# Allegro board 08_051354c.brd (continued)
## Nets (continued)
UNNAMED_7_CAP_I150_N1: C21.1 R76.2(N2)
UNNAMED_7_CAP_I151_N2: A1.6 C29.2(N2) R31.1
UNNAMED_7_CAP_I152_N1: A1.4 C65.1 R33.1
UNNAMED_7_ICFAN3121_I89_EN: R117.2(N2) R118.1 U6.3
UNNAMED_7_ICFAN3121_I89_IN: R5.2(N2) U6.2
UNNAMED_7_MN34906BL_I91_HL: R66.2(N2) U1.17
UNNAMED_7_RES_I93_N2: Q1.5 Q1.6 R26.2(N2)
UNNAMED_10_ADDI9036_I362_AUXINA: C57.2(N2) R72.1 R73.2(N2) RT1.2(N2) U4.E7
UNNAMED_10_ADDI9036_I362_DNC3: R89.1 U4.E3
UNNAMED_10_ADDI9036_I362_DNC4: R88.1 U4.F4
UNNAMED_10_ADDI9036_I362_I2CSCL: R28.2(N2) R41.2(N2) U4.G5
UNNAMED_10_ADDI9036_I362_I2CSDA: R3.2(N2) R6.2(N2) U4.F5
UNNAMED_10_ADDI9036_I362_MTEST: R2.2(N2) U4.K3
UNNAMED_10_FERRITE_I381_N1: C5.1 E1.1 R1.2(N2) Y1.4(VDD)
UNNAMED_10_ICAT24CM01_I285_A2: R47.1 R54.2(N2) U5.3
UNNAMED_10_ICAT24CM01_I285_WP: R55.1 R60.2(N2) U5.7(WP)
UNNAMED_10_RES_I124_N1: R1.1 Y1.1
UNNAMED_10_RES_I290_N1: R62.1 R63.2(N2) U5.2
UNNAMED_10_RES_I374_N1: R110.1 Y1.3
UNNAMED_12_ADT7410_I215_A0: R105.1 R106.2(N2) U13.3
UNNAMED_12_ADT7410_I215_A1: R102.1 R103.2(N2) U13.4
UNNAMED_12_ICFSA642_I1_OEN: R90.2(N2) U7.8
UNNAMED_12_ICFSA642_I193_OEN: R84.1 U11.8
UNNAMED_12_ICPCA9517A_I144_EN: R101.1 U8.5
UNNAMED_12_ICPCA9517A_I227_EN: R24.2(N2) U9.5
UNNAMED_12_ICPCA9517A_I229_EN: R4.2(N2) U14.5
UNNAMED_12_RES_I54_N1: R91.1 S1.1(NO)
UNNAMED_12_RES_I55_N2: R36.2(N2) S1.3
VD: U4.F1
VL: R10.1 R53.2(N2) R70.2(N2)
VL_AFE: C20.2(N2) C27.1 R10.2(N2) U4.K11(VL)
VLD: P21.2 P21.4 P21.6 P21.8 P21.10 P21.12 P21.14 P21.16 P21.18(N9) P21.20 P21.22 P21.24 R25.1 R39.1 R108.2(N2)
VSUB: C44.1 C55.1 C64.1 R8.2(N2) R56.1 R111.1 R117.1 U6.1 U6.8(VDD2)

Pads without a net: P1 11 12 16 17 18 19 20 21 22 23 24 25 26 27 28 29 30; P3 3 5 15 17 20 21 22 23 26 27 28 29 33 35 36 38 39 41 45 47 51 53 57 59 60; P4 3 4 5 6 7 9 11 12 13 14 16 18 20 22 30 31 32 33 34 35 36 37 38; P21 17 19 21 23 25 26 28 41 43 45 47 49 51 53 55 57 59; S2 3; U1 1 7 10 12 25 26 31 32 34 38; U2 24 26 27; U3 6; U4 D4 D5 E5 F6 F7 F8 F9 G6 G7 H6 K5 K9 L2 L3 L9; U5 1; U7 7 24; U10 3 4 8; U11 7 24

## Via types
v1: diameter 0.508, hole 0.254, TOP to BOTTOM, 317 vias
v2: diameter 0.635, hole 0.305, TOP to BOTTOM, 227 vias
v3: diameter 0.457, hole 0.203, TOP to BOTTOM, 19 vias
v4: diameter 0.254, hole 0.127, TOP to L2_GND, 73 vias
v5: diameter 0.254, hole 0.127, L2_GND to L3_SIG, 35 vias

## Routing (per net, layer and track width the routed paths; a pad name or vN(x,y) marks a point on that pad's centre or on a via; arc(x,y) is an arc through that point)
5V_LD: length 4.7
  BOTTOM w0.254: U2.16 22.8,29.53 v1(22.61,29.34)
  BOTTOM w0.279: U2.19 22.86,31.03 22.86,31.04 ; 22.78,31.52 22.8,31.53 U2.20
  BOTTOM w0.508: R15.1 21.84,22.99 v1(21.97,23.11) ; v1(32.24,23.85) 32.05,24.04 32.03,24.04 31.81,24.26 R16.1
  vias: v1(50.5,23.44) v1(50.5,22.68) v1(50.47,21.92) v1(50.47,21.16) v2(7.49,23.37) v2(7.49,22.35) v2(7.49,21.34) v2(8.51,21.34) v2(8.64,23.38) v2(9.53,23.38) v2(16.76,33.4) v2(16.76,32.26) v2(16.76,30.99) v2(17.78,33.4)
5VCC: length 11
  TOP w0.508: R35.1 v1(34.29,22.61) ; R37.1 v1(38.95,10.29) ; R85.1 v1(37.47,22.61) ; R75.1 v1(42.63,10.25)
  BOTTOM w0.508: v1(5.58,30.86) 5.58,30.81 5.57,30.79 E2.2 5.57,27.14 E3.1 2.62,27.01 C49.2
  vias: v1(22.4,19.56) v1(22.43,18.8) v1(23.11,19.56) v1(23.11,18.8)
9VDD: length 127.6
  TOP w0.133: U4.K10 77.92,25.43
  TOP w0.305: 77.92,25.43 78.32,25.83 79.46,25.83 79.72,25.56 C15.1
  TOP w0.508: C15.1 80.36,25.52 81.29,25.52 C12.1 82.86,24 85.6,24 v1(86.11,24.51) ; R9.1 v2(115.87,21.34)
  L8_SIG w0.305: v1(95.83,7.75) v1(95.07,7.75) 92.82,7.75 90.53,10.03 80.14,10.03 77.98,7.87 69.7,7.87 64.67,2.85 30.88,2.85 24.08,9.65 24.08,13.31 21.21,16.18 21.21,20.45 14.22,27.43 14.22,34.7 v1(10.63,38.3)
  BOTTOM w0.133: R26.1 110.81,26.99 110.54,26.72 Q1.4
  BOTTOM w0.254: R26.1 v2(112.27,26.99)
  BOTTOM w0.508: R71.2 v2(93.82,24.38) ; R104.1 v1(10.63,38.3)
GND: length 303.6
  TOP w0.133: v2(100.98,11.68) 101.54,11.12 U12.C2
  TOP w0.165: U4.D6 v4(73.9,23.41)
  TOP w0.254: v1(61.72,22.23) 61.67,22.17 P21.34 ; 45.73,21 P1.7 ; 73.36,34.68 C6.2 ; A1.PAD A1.2 109.6,22.48 109.58,22.5 109.55,22.48 v1(109.45,22.58) ; 41.21,6.33 C85.2 41.21,5.1 ; v1(60.83,18.75) 60.82,18.75 60.18,18.11 59.48,18.11 59.42,18.17 P21.50 ; 82.29,9.01 C69.1 81.55,9.71 ; U4.B7 v4(73.9,23.41) ; C11.2 80.07,29.42 ; v1(62.26,17.02) 61.33,16.09 59.46,16.09 59.39,16.16 P21.58 ; 83.05,38.29 U8.4 84.06,38.9 ; v4(73.4,22.41) U4.C5 ; 45.73,15 P1.1 ; 74.47,16.32 C54.2 73.73,17.02 ; U4.G10 v4(76.4,24.91) v4(76.9,24.91) ; v1(59.46,17.17) P21.54 ; v4(74.9,24.41) U4.E10 U4.D10 v4(73.9,24.91) U4.C9 v4(73.4,24.41) ; 45.73,18 P1.4 ; 82.46,9.27 U13.7 ; C82.1 83.8,21.64 ; 38.67,5.1 C84.2 ; v1(60.83,20.17) P21.42 ; P21.30 59.11,23.17 59.78,23.84 v1(59.78,24.2) ; P21.46 v1(59.42,19.17) ; U4.E2 v4(74.4,20.91) ; v1(59.44,21.17) P21.38 ; DS1.C 12.42,37.1 ; Q2.4 17.03,40.22 ; U4.B3 v4(73.9,21.41) ; 12.42,43.57 12.42,43.46
  TOP w0.305: P21.PAD2 v2(55.05,29.08) P21.PAD1 v2(55.05,32.73) ; Q2.1 15.08,37.66 ; Q2.1 15.73,38.36 ; Q2.1 v1(15.73,36.93) ; v2(55.05,13.01) P21.PAD4 v2(55.05,16.73) P21.PAD3 ; C16.2 69.52,20.82 69.5,20.8 v1(69.32,20.99) ; C23.2 v1(69.16,18.66) ; v2(81.76,38.61) 82.06,38.9 U8.4 ; v1(69.35,19.67) 69.36,19.65 69.37,19.65 69.41,19.62 69.41,19.62 69.48,19.55 C31.2 ; 17.69,39.56 Q2.4 17.03,38.9 ; C85.2 v1(40.39,5.71) ; 26.19,17.81 25.39,18.6 U10.19 ; U10.13 20.42,21.31 ; C26.2 v1(69.35,25.7) ; C14.2 70.15,22.59 v1(69.92,22.35) ; v1(75.49,16.76) C19.2 ; C84.2 v1(39.5,5.71) ; v1(71.63,16.64) 72.05,16.64 C53.1 ; U10.2 27.67,20.81 v1(27.94,21.08)
  TOP w0.381: v2(99.49,19.81) 99.23,19.55 U1.20 ; U1.29 97.31,25.76 v2(97.07,25.53)
  TOP w0.406: U1.24 99.35,22.51 ; v2(99.45,21.21) U1.22 ; U1.6 v2(90.25,23.16)
  TOP w0.508: v2(103.38,12.97) 103.38,12.33 C79.2 104.65,12.31 v2(104.65,12.97) ; C72.2 v1(27.81,24.29) ; v1(78.84,14.35) 79.02,14.53 C77.1 ; C24.2 v1(62.52,22.41) ; C57.1 72.91,34.6 v1(72.89,34.62) ; P1.1 46.96,14.36 v2(47.12,14.21) ; v2(72.27,4.29) 73.35,4.29 C1.1 73.66,3.62 ; 91.2,13.78 R103.1 v2(92.22,12.95) ; C67.1 27.27,43.27 ; C67.1 27.27,41.19 ; C67.1 v2(26.16,42.16) ; v1(3.29,36.7) R36.1 4.02,35.81 ; v1(32.26,24.77) 32,24.51 R48.2 ; C86.1 50.7,11.47 ; C86.1 51.68,10.16 ; C86.1 49.72,10.16 ; C86.1 50.7,8.85 ; C13.2 v1(84.39,33.21) ; C13.2 v1(82.68,34.92) ; C13.2 v1(80.64,33.21) ; v1(69.39,34.82) 69.65,34.57 70.24,34.57 RT1.1 70.37,35.23 70.35,35.26 v1(70.35,35.26) ; C77.1 80.03,15.35 ; C77.1 77.97,15.35 ; 14.47,7.18 P31.2 ; P31.2 14.47,3.58 ; P31.2 12.65,5.38 ; P31.2 16.18,5.38 v2(16.51,5.71) ; 16.08,11.48 P31.3 ; P31.3 14.47,9.68 ; P31.3 14.47,13.28 ; P31.3 14.44,11.51 v2(12.78,11.51) ; v1(115.32,25.76) C29.1 114.47,26.49 ; C69.1 v2(80.54,9.01) ; v1(64.55,29.64) C61.2 66.34,29.16 67.9,27.6 C10.2 ; C83.1 71.37,29.6 v1(71.37,30.31) ; v2(48.3,23.31) 48.3,23.49 47.79,24 P1.10 ; C5.2 v1(65.31,25.38) ; 74.27,35.66 C6.2 v1(75.18,34.68) ; v1(78.25,29.41) 78.26,29.42 C11.2 79.17,30.3 ; C33.2 v1(76.88,16.36) ; C33.2 76.18,17.07 ; C33.2 77.7,17.07 ; R73.1 72.01,34.14 v1(72.01,34.67) ; v1(21.34,25.03) C74.2 ; v1(70.14,14.19) C7.2 ; C63.1 81.65,42.16 ; C63.1 v2(80.91,43.37) ; C63.1 80.18,42.16 ; P1.4 v1(48.69,18) ; C62.1 v2(113.84,20.57) 113.84,19.81 113.2,19.18 C65.2 112.56,18.44 ; R57.2 96.36,8.92 95.81,8.92 95.63,9.09 ; v2(16.56,6.99) 16.59,7.01 R23.2 ; P1.7 48.52,21 v1(48.69,20.83) ; U13.7 v2(85.74,9.27) ; 90.56,42.01 C68.2 v2(91.96,41.27) ; R18.1 v2(15.01,19.77) ; v2(100.98,11.68) C81.2 ; C81.2 v2(97.87,11.68) ; C81.2 99.45,12.89 ; R106.1 v2(92.2,9.41) ; v1(84.03,26.71) C20.1 83.27,26.59 C12.2 v1(84.16,25.19) ; Y1.2 v2(61.45,24.89) ; 12.42,43.46 DS3.C ; A1.PAD v2(111.3,23.58)
  TOP w0.762: v1(13.74,39.24) DS2.C 12.42,40.59 12.42,40.59 12.42,40.59 DS3.C 13.72,42.42 ; C82.1 82.92,20.51 ; v1(12.42,34.31) DS1.C 13.84,35.94
  L2_GND w0.203: v1(71.74,22.19) 71.74,22.2
  L9_GND w0.203: 22.41,35.68 22.41,35.5 22.73,35.18 22.91,35.18 ; 23.24,36.7 23.41,36.53 23.41,35.68 ; 22.48,37.72 22.23,37.47 22.23,36.96 22.91,36.27 22.91,35.68 ; 23.92,37.34 23.92,35.68 ; 22.1,33.66 23.41,34.97 23.41,35.18
  BOTTOM w0.133: U11.9 54.06,11.99 C87.1
  BOTTOM w0.203: U7.9 74.25,10.15 74.67,9.74 C56.1
  BOTTOM w0.254: v1(25.78,27.43) 25.6,27.61 U2.11 ; U2.1 26.8,32.53 26.78,32.52 26.55,32.52 v2(26.29,32.26) ; U2.PAD 24.6,30.03 U2.17 ; v2(24.38,32.26) 24.12,32.52 23.92,32.52 23.9,32.53 U2.22
  BOTTOM w0.279: 28.12,29.87 27.95,30.03 U2.6 26.1,30.03 U2.PAD
  BOTTOM w0.305: U6.5 99.86,15.33 v2(100.23,15.7) 100.59,15.33 U6.4 ; v2(15.49,13.36) 15.54,13.41 U3.14 ; U5.4 v2(44.77,20.31) ; U5.4 44.15,18.92 ; U5.4 44.77,17.36 44.7,17.3 ; 15.7,17.68 16.96,16.42 U3.18 ; 73.67,24.52 C2.2 74.29,25.14 ; 72.99,24.55 C8.2 72.28,25.13 ; U3.5 21.81,13.41
  BOTTOM w0.381: 47.27,14.38 47.12,14.23 v2(47.12,14.21) ; U9.4 70.23,34.34 69.75,34.82 v1(69.39,34.82) ; C70.1 v1(66.22,31.99) ; D6.C v2(102.79,33.53)
  BOTTOM w0.406: v2(102.54,34.54) 102.35,34.54 101.94,34.14 D6.C
  BOTTOM w0.508: v2(78.66,10.11) R90.1 77.56,9.33 ; 39.55,43.45 39.55,43.18 ; P3.19 v2(57.89,4.29) ; C75.2 78.76,29.87 ; P3.58 73.09,5.52 ; R20.2 v2(18.33,6.48) ; P3.30 v2(61.89,8.73) ; R14.2 21.83,25.28 ; R14.2 23.8,25.28 C37.1 ; R14.2 v2(22.73,24.13) ; 81.41,21.25 R2.1 80.69,22.03 ; P3.49 v2(69.89,4.29) ; v2(54.69,5.51) P3.12 ; R60.1 47.9,29.28 v2(48.23,29.62) ; R54.1 v2(43.96,14.1) ; C42.2 v1(9.86,32.77) ; v2(47.12,14.21) 47.27,14.36 R63.1 ; R29.2 v2(106.88,28) ; v2(72.27,4.29) 72.29,4.27 P3.55 ; v2(103.38,12.97) 103.13,12.72 R38.2 ; P3.52 70.69,8.97 70.71,8.99 v2(70.71,9.03) ; v2(104.65,12.97) 104.65,12.95 104.41,12.71 C80.2 ; P3.37 v2(65.09,4.29) ; 47.67,24.09 C52.2 49.34,24.09 ; P3.40 65.89,8.58 v2(65.75,8.71) ; 77.55,43.45 77.55,43.33 ; C98.2 v1(20.57,28.83) ; P3.13 v2(55.49,4.27) ; R27.2 v2(110.59,30.41) ; P3.6 v2(52.29,5.59) ; P3.24 v2(59.49,8.73) ; v2(108.4,25.1) 108.16,24.85 C18.2 ; C97.2 v1(21.46,28.83) ; P3.31 v2(62.69,4.38) ; P3.43 v2(67.49,4.29) ; 74.67,8.39 C56.1 v1(75.44,9.27) ; P3.25 v2(60.29,4.29) ; C30.2 v2(109.42,30.43) ; P3.18 v2(57.09,8.73) ; P3.46 v2(68.29,8.73)
  BOTTOM w0.584: 107.55,24.15 107.51,24.15 C18.2 ; C76.2 v2(92.71,22.61) ; 105.91,27.27 R29.2 ; C52.2 48.41,23.43 v2(48.3,23.31) ; 105.15,11.68 C80.2 ; 111.36,29.61 R27.2
  BOTTOM w0.762: P4.1 39.55,36.89 39.24,36.58 38.63,36.58 ; P4.1 39.55,38.07 39.29,38.33 38.71,38.33 ; P4.1 38.65,37.42 ; R90.1 77.56,10.88 ; 101.94,32.92 D6.C ; v2(38.38,41.72) 38.43,41.68 P4.2 39.55,43.18 ; 103.13,11.29 R38.2 ; 43.19,15.5 R54.1 ; 68.29,5.78 P3.46 ; v2(77.55,35.42) P4.39 78.46,37.42 ; v2(78.7,41.68) P4.40 77.55,43.33 ; R63.1 48.04,15.5
  vias: v1(17.73,40.13) v1(50.42,25.04) v1(50.43,24.3) v1(60.25,30.18) v1(60.24,28.14) v1(60.24,26.17) v1(61.09,14.02) v1(62.13,14.05) v1(63.45,22.25) v1(63.78,16.89) v1(64.47,14.1) v1(64.62,22.25) v1(64.9,16.84) v1(65.66,20.22) v1(67.51,16.79) v1(69.25,22.58) v1(72.52,28.96) v1(73.02,30.6) v1(81.55,14.61) v1(82.01,20.77) v1(83.87,21.27) v2(1.65,25.53) v2(2.54,25.53) v2(3.27,22.42) v2(3.43,25.53) v2(4.25,22.86) v2(4.25,21.97) v2(5.21,23.5) v2(6.22,23.5) v2(10.16,15.62) v2(10.92,16) v2(11.43,6.48) v2(11.43,5.59) v2(11.43,4.7) v2(11.56,15.49) v2(12.19,16) v2(12.57,4.06) v2(12.57,3.17) v2(12.78,13.31) v2(12.78,12.45) v2(18.03,21.59) v2(18.29,14.86) v2(18.29,13.46) v2(18.92,21.59) v2(18.96,14.16) v2(19.6,14.86) v2(19.56,13.46) v2(21.72,12.19) v2(21.72,11.33) v2(24.08,22.15) v2(24.08,21.34) v2(24.08,20.45) v2(24.38,30.73) v2(24.38,29.34) v2(24.6,7.18) v2(24.6,5.02) v2(24.89,22.15) v2(24.89,21.34) v2(24.89,20.45) v2(25.53,4.06) v2(25.71,22.15) v2(25.71,21.34) v2(25.7,20.45) v2(26.29,30.73) v2(26.29,29.34) v2(26.37,4.06) v2(27.18,4.06) v2(27.99,4.06) v2(28.24,16.71) v2(28.24,15.7) v2(28.24,14.68) v2(29.08,28.57) v2(29.91,27.69) v2(29.89,16.71) v2(29.89,15.7) v2(30.99,26.44) v2(31.88,26.44) v2(32.77,26.44) v2(34.77,26.42) v2(36.04,26.42) v2(36.58,27.81) v2(72.14,5.33) v2(75.15,6.32) v2(93.14,10.11) v2(100.25,21.97) v2(100.25,16.94) v2(100.88,22.99) v2(101.65,21.34) v2(102.28,22.1) v2(103.12,30.99) v2(103.12,29.97) v2(104.14,30.99) v2(104.14,29.97) v2(106.6,20.73) v2(106.6,19.71) v2(106.6,18.69) v2(106.6,17.68) v2(106.6,16.66) v2(107.53,17.73) v4(72.57,28.3) v4(73.4,20.91) v4(73.58,27.43) v4(73.9,20.91) v4(74.4,24.41) v4(74.4,21.41) v4(74.52,28.38) v4(74.9,21.91) v4(75.9,20.91) v4(76.2,28.3) v4(76.96,28.3) v4(77.4,20.91) v4(77.9,22.91) v4(79.36,18.08) v4(80.32,27.48) v4(80.31,24.61) v4(80.31,21.32)
V1: length 18.8
  TOP w0.133: v1(90.1,27.41) 90.59,27.9 92.82,27.9 93.21,27.52 U1.37
  L2_GND w0.14: v5(78.53,24.94) 77.43,24.94 v4(76.9,24.41)
  L3_SIG w0.102: v5(78.53,24.94) 78.53,25.3 79.43,26.2 88.89,26.2 v1(90.1,27.41)
V2: length 16.5
  TOP w0.133: U1.3 90.31,25.11 89.99,25.44 88.63,25.44 v1(88.1,24.91)
  L2_GND w0.14: v5(79.04,24.94) 78.66,24.56 77.55,24.56 v4(76.9,23.91)
  L3_SIG w0.102: v5(79.04,24.94) 79.04,24.9 79.08,24.86 79.08,24.8 79.46,24.42 80.08,24.42 80.92,25.26 83.12,25.26 83.71,24.66 85.27,24.66 85.83,25.22 87.79,25.22 v1(88.1,24.91)
V3: length 31.8
  TOP w0.133: v1(93.32,29.66) 93.32,28.23 93.86,27.69 U1.36
  L2_GND w0.14: v1(75,30.2) 74.47,29.67 74.47,28.96 74.93,28.5 74.93,27.2 74.36,26.63 74.36,25.48 75.53,24.32 75.53,23.73 75.85,23.41 v4(76.4,23.41)
  L3_SIG w0.102: v1(75,30.2) 75.84,31.03 76.76,31.03 77.77,32.05 77.79,32.05 77.81,32.07
  L3_SIG w0.178: v1(93.32,29.66) 92.69,29.66 90.28,32.07 77.81,32.07
V4: length 14.3
  TOP w0.133: U1.4 89.75,24.46 v1(89.49,24.72) ; v5(79.55,24.94) 79.17,24.94 79.14,24.91 U4.L10
  L3_SIG w0.102: v5(79.55,24.94) 80.34,25.73 88.48,25.73 v1(89.49,24.72)
V9: length 17.4
  TOP w0.133: U1.2 90.53,25.76 90.21,26.09 86.69,26.09 v1(85.34,27.43)
  L3_SIG w0.102: v5(76.9,23.41) 76.9,23.43 77.31,23.84 77.31,24.75 79.99,27.43 v1(85.34,27.43)
V10: length 23.1
  TOP w0.133: v1(89.96,18.41) 92.96,18.41 93.21,18.66 U1.13
  L2_GND w0.14: v4(77.4,23.91) 77.67,24.17 v5(78.53,24.17)
  L3_SIG w0.102: v1(89.96,18.41) 90.55,18.41 91.19,19.05 91.19,20.83 90.68,21.33 87.4,21.33 85.06,23.68 80.96,23.68 80.71,23.42 79.02,23.42 78.53,23.9 v5(78.53,24.17)
V11: length 21.1
  TOP w0.133: U1.14 93.86,18.4 93.23,17.78 90.61,17.78 90.58,17.75 v1(90.08,17.75)
  L3_SIG w0.102: v1(90.08,17.75) 88.99,17.75 84.48,22.26 81.95,22.26 81.65,21.96 78.65,21.96 78.04,22.57 76.56,22.57 v5(76.4,22.41)
V12: length 20.9
  TOP w0.133: U1.35 94.51,28.03 v1(94.46,28.08) ; v1(87.31,24.35) 86.07,23.11 80.59,23.11 79.79,23.91 U4.L8
  BOTTOM w0.133: v1(87.31,24.35) 87.31,25.57 88.18,26.45 90.59,26.45 92.23,28.08 v1(94.46,28.08)
V13: length 16
  TOP w0.133: U1.8 90.45,21.86 v1(90.12,22.19)
  L2_GND w0.14: v4(77.4,23.41) 77.78,23.79 78.66,23.79 v5(79.04,24.17)
  L3_SIG w0.102: v1(90.12,22.19) 87.21,22.19 85.25,24.15 83.33,24.15 82.69,24.79 81.2,24.79 80.3,23.89 79.32,23.89 v5(79.04,24.17)
V14: length 16.2
  TOP w0.133: U1.11 90.6,19.55 v1(90.34,19.81)
  L3_SIG w0.102: v5(76.9,22.91) 78.37,22.91 78.85,22.43 81.36,22.43 81.66,22.74 84.67,22.74 87.59,19.81 v1(90.34,19.81)
V15: length 16
  TOP w0.133: v1(90.31,20.57) 90.31,21.01 90.51,21.21 U1.9
  L2_GND w0.14: v5(79.04,22.9) 78.66,23.29 77.78,23.29 v4(77.4,22.91)
  L3_SIG w0.102: v5(79.04,22.9) 80.93,22.9 81.23,23.21 84.86,23.21 87.5,20.57 v1(90.31,20.57)
V16: length 14.3
  TOP w0.133: U4.L7 79.64,23.41 80.44,22.61 86.36,22.61 87.57,23.81 U1.5
VCC: length 6.8
  TOP w0.508: 17.27,27.56 v1(16.26,27.56)
  BOTTOM w0.254: U2.8 v1(27.24,28.45) ; U2.12 25.1,26.53 25.15,26.48 ; C37.2 24.6,26.57 U2.13
  BOTTOM w0.508: v1(25.78,26.48) C37.2
  vias: v2(37.62,25.93) v2(38.76,25.93) v2(40.01,25.93) v2(40.01,24.79)
1P8VDD: length 42.4
  TOP w0.133: U4.B11 72.51,26.3 72.51,26.6 ; 72.03,23.22 72.34,22.91 U4.A6 ; U4.H11 76.4,25.8 ; U4.K1 77.61,20.2 ; U4.L5 78.27,22.41
  TOP w0.254: U4.B6 U4.A6
  TOP w0.305: 71.69,27.68 72.51,27.68 C28.1 ; C17.1 v1(76.96,27.1) 76.96,26.79 76.4,26.23 76.4,25.8 ; 79.04,16.98 78.72,17.3 C25.1 78.72,19.09 77.61,20.2 ; 78.27,22.41 78.72,21.95 C22.1 80.95,21.95 81.26,21.64 C82.2 ; C19.1 v1(75.49,18.71) 74.9,19.3 U4.E1 ; 72.03,23.22 C14.1 69.05,23.22 68.43,22.59 v1(68.43,22.53) ; C23.1 v1(71.12,18.66) 71.49,18.66 73.2,20.36 73.36,20.36 U4.B1
  TOP w0.381: 72.51,26.6 C28.1 ; C82.2 81.25,21.57 81.25,20.53 v1(81.23,20.53)
  TOP w0.508: v1(64.13,32.12) R119.2 ; C77.2 79.08,17.01 v1(80.02,17.01) ; C6.1 74.27,32.06 73.76,31.56 v1(73.03,31.56) ; v1(70.48,29.08) 70.48,28.88 C83.2 71.69,27.68 ; v2(66.58,24.32) 66.58,24.35 66.57,24.36 E1.2 ; R72.2 68.44,34.24 v2(68.44,34.51)
  L3_SIG w0.203: v5(75.9,21.41) 75.77,21.28 75.21,21.28 75.03,21.11
  L3_SIG w0.305: v1(75.49,18.71) 74.68,19.52 74.68,20.75 75.03,21.11
  BOTTOM w0.508: v2(91.31,17.02) 91.31,18.3 92.44,19.43 D4.A
  vias: v2(15.53,22.67) v2(15.58,23.69) v2(16.47,23.69)
2P1VDD: length 1.9
  BOTTOM w0.254: U3.21 18.71,17.64 v1(18.97,17.91)
  vias: v2(17.65,5.21) v2(17.65,4.06) v2(18.67,4.06)
3P3VDD: length 32.8
  TOP w0.133: 76.96,26.01 76.9,25.95 U4.J11 ; 72.52,25.12 72.73,24.91 U4.A10 ; 71.92,21.41 72.42,21.91 U4.A4 ; U4.A2 72.61,20.62 ; U4.D1 74.4,19.79 74.34,19.73 ; U4.G11 75.9,25.92 ; U4.E11 74.9,25.69 74.76,25.83 74.4,25.83 U4.D11
  TOP w0.305: v1(71.13,19.55) 71.54,19.55 72.61,20.62 ; 72.52,25.12 71.94,25.7 v1(71.21,25.7) C26.1 ; 71.92,21.41 v1(71.21,20.7) 71.19,20.72 71.18,20.72 71.13,20.77 70.65,20.77 C16.1 ; 76.96,26.01 77.85,26.9 77.85,26.92 ; U4.A8 72.61,23.91 72.42,24.11 72.41,24.11 72.39,24.11 72.27,24.23 71.87,24.23 71.82,24.23 71.8,24.26 71.69,24.26 v1(71.29,24.66) ; v1(73.93,28.05) 74.23,27.74 C60.1 74.52,27.3 74.25,27.03 74.25,25.99 74.4,25.83 ; 74.34,19.73 74.34,18.99 v1(74.6,18.73) ; 75.9,25.92 75.9,26.49 76.2,26.79 v1(76.2,27.1) C58.1
  TOP w0.381: C11.1 78.27,26.92 77.85,26.92 ; v1(71.13,19.55) C31.1 ; C54.1 74.6,18.15 v1(74.6,18.73)
  TOP w0.508: C10.1 69.5,29.27 C61.1 69.6,30.1 v1(70.48,30.1) ; C13.1 81.18,29.81 81.18,29.34 v1(80.19,28.35) 79.7,28.35 79.17,27.82 C11.1 ; v1(70.14,17.02) R65.2
3P5VDD: length 112.9
  TOP w0.133: 73.84,20.11 73.9,20.18 U4.C1
  TOP w0.254: v1(50.62,28.17) 50.62,28.17 P21.9
  TOP w0.305: v1(71.63,18.02) C53.2 72.44,18.73 72.88,19.17 72.9,19.17 73.84,20.11 ; C68.1 89.13,40.85 U8.8
  TOP w0.508: v1(62.15,32) R120.1 ; S5.1 v1(20.83,39.88) ; v1(80.67,8.01) C69.2 83.95,8.01 83.96,8 ; v1(30.19,1.68) 29.53,1.68 29.44,1.59 21.03,1.59 20.78,1.84 R22.2 ; C68.1 v2(89.56,42.29) ; v1(4.13,42.28) R91.2 ; R101.2 v2(91.96,38.1) ; v1(55.19,11.33) 55.19,10.67 54.69,10.16 C86.2 ; v1(73.66,8.62) C1.2 ; R74.1 91.59,39.12 91.96,39.49 v2(91.96,40.13) R82.1
  L3_SIG w0.508: v1(30.19,1.68) 41.83,1.68 49.61,9.46 60.14,9.46 v1(60.86,10.19)
  BOTTOM w0.133: U11.10 54.16,11.59 C87.2
  BOTTOM w0.203: U7.10 73.86,9.95 73.67,9.76 C56.2
  BOTTOM w0.381: U9.8 75.99,31.28 76.28,31
  BOTTOM w0.508: R105.2 v2(91.2,8.26) ; v1(60.86,10.19) 63.86,13.18 65.18,13.18 69.68,17.69 71.3,17.69 v1(71.63,18.02) ; v1(55.19,11.33) 55.19,11.34 C87.2 ; v1(54.1,33.91) 54.1,28.7 54.86,27.94 R83.2 55.25,26.66 56.24,25.68 C89.1 56.24,23.92 U14.8 ; R94.2 79.28,31.75 v1(80.1,30.93) ; v1(77.69,29.91) 77.69,30.61 C75.1 76.59,30.68 76.28,31 ; v1(73.66,8.62) 73.67,8.63 C56.2 ; R93.2 R24.1 v2(78.75,34.59) ; v2(90.17,12.95) R102.2 ; v1(49.94,28.17) v1(50.62,28.17) 50.62,27.61 51.57,26.66 R4.1 R81.2
3P5VDD_RPI: length 31.7
  TOP w0.508: P1.15 46.39,29 45.28,30.1 v1(44.83,30.1) ; 29.59,39.88 29.38,39.88 28.87,40.39 C67.2 v2(29.97,42.16)
  L8_SIG w0.508: v2(29.97,42.16) 29.97,36.32 30.61,35.69 42.74,35.69 43.94,34.48 43.94,30.99 v1(44.83,30.1)
AFE_GPO1: length 27.5
  TOP w0.133: v1(95.12,27.94) 95.5,27.94 95.81,27.64 U1.33
  L2_GND w0.14: v1(76.26,29.29) 75.73,28.75 75.73,27.31 75.71,27.3 75.71,26.89 75.73,26.88 75.73,24.59 v4(75.9,24.41)
  L3_SIG w0.102: v1(76.26,29.29) 76.66,28.9 78.58,28.9 79.62,29.94 89.51,29.94 92.04,27.41 94.59,27.41 v1(95.12,27.94)
AFE_GPO2:
  vias: v4(75.9,23.91) v5(75.9,23.91)
AFE_GPO3: length 97.3
  TOP w0.133: R114.2 106.67,13.08 v1(105.79,13.08) ; v1(73.66,17.66) v4(73.66,18.41) ; v1(38.47,19.43) R96.2
  L2_GND w0.14: v4(75.4,21.41) 75.4,20.74 73.66,19 v4(73.66,18.41)
  L3_SIG w0.102: v1(73.66,17.66) 70.74,14.74 70.74,14.07 70.21,13.54 67.74,13.54 65.49,11.28 60.37,11.28 59.33,12.33 59.33,13.44 57.15,15.62 54.56,15.62 54.13,16.05 41.84,16.05 v1(38.47,19.43)
  BOTTOM w0.133: v1(105.79,13.08) 107.19,11.68 107.19,10.54 104.14,7.49 98.48,7.49 97.7,8.27 92.98,8.27 92.13,7.42 84.26,7.42 80.64,11.03 80.64,13.72 79.38,14.99 76.1,14.99 74.8,16.28 74.8,16.51 v1(73.66,17.66)
AFE_GPO4: length 107.2
  TOP w0.133: v1(35.29,21.72) R92.2
  L3_SIG w0.102: v1(18.19,26.8) 17.91,27.08 17.91,28.01 18.47,28.57 19.56,28.57 22.48,25.65 32.13,25.65 35.29,22.49 v1(35.29,21.72) 41.46,15.54 53.82,15.54 56.13,13.23 v1(56.13,11.81) ; v1(64.23,8.74) 64.23,7.68 65.07,6.84 72.75,6.84 74.67,8.76 78.12,8.76 82.27,12.91 82.27,19.48 82.6,19.81 84.33,19.81 84.71,20.19 84.71,21.34 84.26,21.79 82.24,21.79 81.95,21.5 78.58,21.5 77.81,22.26 76.75,22.26 v5(76.4,21.91)
  L8_SIG w0.102: v1(56.13,11.81) 56.13,8.2 57.23,7.11 63.5,7.11 64.23,7.84 v1(64.23,8.74)
  BOTTOM w0.133: v1(18.19,26.8) 18.19,25.89 R116.2
AFE_GPO6: length 22.5
  TOP w0.133: v1(85.74,18.58) 85.14,18.58 85.13,18.57 80.32,18.57 79.46,19.43 v4(79.46,19.81)
  L2_GND w0.14: v4(77.4,21.91) 77.45,21.91 78.93,20.44 78.93,20.31 79.42,19.81 v4(79.46,19.81)
  L3_SIG w0.102: v1(85.74,18.58) 87.53,16.79 89.64,16.79 v1(94.49,11.94)
  BOTTOM w0.133: v1(94.49,11.94) 94.5,11.93 R118.2
AFE_GPO7: length 62.4
  TOP w0.133: LD_EN1.2 v1(49.78,34.92)
  L3_SIG w0.102: v1(83.89,20.51) 82.63,20.51 82.13,20.01 80.73,20.01 79.72,21.03 78.52,21.03 77.64,21.91 v5(76.9,21.91) ; v1(64.28,39.24) 63.12,39.24 62.36,38.48 53.34,38.48 v1(49.78,34.92)
  L8_SIG w0.102: v1(83.89,20.51) 84.84,21.46 84.84,30.55 73.41,41.99 66.37,41.99 64.28,39.9 v1(64.28,39.24)
AFE_GPO8: length 60.6
  TOP w0.133: LD_EN2.2 v1(48.64,34.92) ; v1(81.74,19.25) 80.65,19.25 v4(79.97,19.93)
  L2_GND w0.14: v4(76.9,22.41) 77.4,22.41 78.68,21.13 79.6,21.13 79.97,20.76 v4(79.97,19.93)
  L3_SIG w0.102: v1(48.64,34.92) 52.7,38.99 61.92,38.99 63.32,40.39 64.04,40.39 65.18,39.24 v1(66.55,39.24)
  L8_SIG w0.102: v1(66.55,39.24) 67.31,40.01 73.38,40.01 76.81,36.57 76.81,34.39 78.76,32.45 78.76,20.39 79.63,19.52 81.47,19.52 v1(81.74,19.25)
AFETEMP_I2C1_SCL: length 39.7
  TOP w0.133: 89.04,8 v1(87.39,8) ; R82.2 89.04,40.13 88.97,40.2 U8.7 86.38,40.2 v1(86.14,40.44)
  BOTTOM w0.133: v1(87.39,8) 88.69,9.3 88.69,21.8 86.63,23.86 86.63,24.73 86.34,25.01 86.34,37.51 86.92,38.1 86.92,39.66 v1(86.14,40.44)
AFETEMP_I2C1_SDA: length 37
  TOP w0.133: R74.2 88.79,39.12 88.35,39.55 U8.6 86.34,39.55 86.14,39.35 v1(86.14,39.31) ; U13.2 v1(87.39,9.27)
  BOTTOM w0.133: v1(86.14,39.31) 86.14,38.09 85.86,37.82 85.86,25.01 85.59,24.73 85.59,24.14 88.17,21.56 88.17,10.05 v1(87.39,9.27)
CCDINA: length 64.6
  TOP w0.133: U4.B10 73.26,25.05 73.26,25.06 73.05,25.27 73.04,25.27 72.02,26.29 68.34,26.29 v1(68.07,26.56) ; v1(111.32,18.17) 110.79,18.17 C21.2
  L3_SIG w0.102: v1(68.07,26.56) 69.96,28.45 73.39,28.45 73.99,29.06 73.99,30.79 76.96,33.76 100.89,33.76 102.62,32.03 104.34,32.03 106.15,30.22 106.15,23.34 v1(111.32,18.17)
CLI: length 10
  TOP w0.133: R110.2 64.86,23.82 65.07,24.03 v1(65.63,24.03)
  L3_SIG w0.102: v5(73.9,22.91) 73.69,23.12 70.78,23.12 70.4,23.5 66.16,23.5 v1(65.63,24.03)
CLK_N: length 16.6
  L3_SIG w0.102: v3(79.12,12.71) 79.1,12.97 79.2,13.08 79.34,13.09 79.84,13.09 81.01,14.25 81.01,18.56 80.26,19.3 79.5,19.3 77.53,21.28 77.03,21.28 v5(76.9,21.41)
  BOTTOM w0.133: v3(79.12,12.71) 78.79,13 78.09,13 77.84,13.25 76.97,13.25 76.53,12.81 75.19,12.81 U7.2
CLK_P: length 16.6
  L3_SIG w0.102: v5(76.9,20.91) 77.03,21.04 77.43,21.04 79.4,19.07 80.17,19.07 80.77,18.46 80.77,14.35 80.29,13.87 80.15,13.87 79.97,14.04 79.83,14.04 79.68,13.9 79.68,13.75 79.86,13.58 79.86,13.44 79.74,13.32 79.34,13.32 79.33,13.32 79.19,13.31 79.08,13.41 v3(79.06,13.67)
  BOTTOM w0.133: U7.1 75.17,13.14 76.39,13.14 76.83,13.59 77.98,13.59 78.23,13.34 78.77,13.34 v3(79.06,13.67)
DATA0_N: length 17.3
  L3_SIG w0.102: v5(76.9,20.41) 76.77,20.28 76.77,20.13 77.11,19.79 77.44,19.79 78.09,19.15 78.09,18.88 78.19,18.78 78.88,18.78 79.12,18.54 79.12,18.15 78.88,17.91 78.19,17.91 78.09,17.8 78.09,17.6 78.19,17.5 78.88,17.5 79.12,17.26 79.12,16.86 78.88,16.62 78.19,16.62 78.09,16.52 78.09,16.32 78.19,16.22 78.88,16.22 79.12,15.98 79.12,15.58 78.88,15.34 78.19,15.34 78.09,15.24 78.09,12.48 77.68,12.07 77.54,12.07 77.4,12.07 77.3,11.96 v3(77.3,11.69)
  BOTTOM w0.133: U7.4 75.62,11.99 75.66,12.02 76.78,12.02 76.96,12.03 v3(77.3,11.69)
DATA0_P: length 17.3
  L3_SIG w0.102: v5(76.4,20.41) 76.53,20.28 76.53,20.04 77.01,19.56 77.34,19.56 77.85,19.05 77.85,18.79 78.09,18.55 78.78,18.55 78.89,18.45 78.89,18.24 78.78,18.14 78.09,18.14 77.85,17.9 77.85,17.5 78.09,17.26 78.78,17.26 78.89,17.16 78.89,16.96 78.78,16.86 78.09,16.86 77.85,16.62 77.85,16.22 78.09,15.98 78.78,15.98 78.89,15.88 78.89,15.68 78.78,15.58 78.09,15.58 77.85,15.34 77.85,15.03 77.7,14.88 77.7,14.62 77.85,14.47 77.85,14.22 77.7,14.07 77.7,13.81 77.85,13.66 77.85,13.41 77.7,13.25 77.7,13 77.85,12.85 77.85,12.57 77.58,12.3 77.54,12.3 77.4,12.3 77.29,12.4 v3(77.29,12.67)
  BOTTOM w0.133: v3(77.29,12.67) 76.99,12.36 76.78,12.36 75.66,12.36 75.62,12.39 U7.3
DATA1_N: length 17.2
  L3_SIG w0.102: v3(75.79,10.64) 75.99,10.84 76.13,10.84 76.35,10.62 76.35,10.26 76.23,10.14 75.28,10.14 74.78,10.64 74.78,10.74 74.89,10.84 75.08,10.84 75.18,10.94 75.18,11.15 75.08,11.25 74.89,11.25 74.78,11.35 74.78,11.55 74.89,11.65 75.08,11.65 75.18,11.76 75.18,11.96 75.08,12.06 74.89,12.06 74.78,12.16 74.78,12.37 74.89,12.47 75.08,12.47 75.18,12.57 75.18,12.77 75.08,12.87 74.89,12.87 74.78,12.98 74.78,13.36 76.31,14.89 76.31,19.4 75.93,19.78 75.93,20.6 76.29,20.97 76.34,20.97 v5(76.4,20.91)
  BOTTOM w0.133: v3(75.79,10.64) 75.84,10.69 75.84,11.06 75.68,11.22 75.55,11.22 75.52,11.19 U7.6
DATA1_P: length 17.2
  L3_SIG w0.102: v3(76.49,11.34) 76.3,11.15 76.3,11 76.58,10.72 76.58,10.16 76.33,9.91 75.18,9.91 74.55,10.54 74.55,13.46 76.07,14.99 76.07,19.3 75.69,19.68 75.69,20.7 v5(76.4,21.41)
  BOTTOM w0.133: v3(76.49,11.34) 76.03,11.34 75.82,11.56 75.56,11.56 75.53,11.59 U7.5
FB: length 5.8
  BOTTOM w0.133: R11.2 R12.1 28.32,26.92 27.69,27.56 27.18,27.56 26.6,28.14 U2.9
H1: length 35.5
  TOP w0.133: U1.28 99.17,25.11 v1(99.45,25.4)
  L2_GND w0.14: v1(75.02,29.1) 75.36,28.76 75.39,28.73 75.39,24.92 v4(75.4,24.91)
  L3_SIG w0.102: v1(75.02,29.1) 75.72,29.8 76.87,29.8 77.48,30.41 77.9,30.41 77.9,30.41 89.99,30.41 91.8,28.6 99.86,28.6 100.35,28.11 100.35,26.29 v1(99.45,25.4)
H2: length 37.8
  TOP w0.133: U4.F11 75.4,27.83 75.55,27.98 75.55,29.37 76,29.82 v1(76,30.32) ; v1(100.08,25.02) 99.52,24.46 U1.27
  L3_SIG w0.102: v1(76,30.32) 76.73,30.32 77.97,31.56
  L3_SIG w0.178: 77.97,31.56 89.81,31.56 92.25,29.12 100.26,29.12 100.99,28.39 100.99,25.99 100.43,25.42 100.43,25.37 v1(100.08,25.02)
HL: length 23.5
  L2_GND w0.14: v4(76.4,24.41) 76.07,24.74 76.07,25.15 77.89,26.97 v5(78.66,26.97)
  L3_SIG w0.102: v1(92.45,25.75) 92.45,26.29 89.57,29.17 80.07,29.17 78.66,27.76 v5(78.66,26.97)
  BOTTOM w0.133: v1(92.45,25.75) 92.45,24.96 91.39,23.89 R66.1
I2C2_SCL: length 110.4
  TOP w0.133: S5.3 21.08,37.34 20.83,37.59 v1(20.83,37.97) 20.83,38.4 21.03,38.61 S5.2
  L3_SIG w0.102: v1(60.26,12.64) 60.26,12.69 59.7,13.25 59.7,13.71 55.37,18.03 49.95,18.03 49.31,18.67 44.67,18.67 42.32,21.02 42.32,25.63 33.27,34.67 20.19,34.67 19.68,35.18 19.68,36.83 v1(20.83,37.97)
  L8_SIG w0.14: v1(60.26,12.64) 60.13,12.51 60.13,9.7 61.66,8.18 61.67,8.18 61.72,8.13 62.07,8.13 62.67,8.73 v1(62.69,8.73)
  BOTTOM w0.133: U14.2 54.15,21.13 54.48,21.46 57.28,21.46 57.91,20.83 57.91,14.99 v1(60.26,12.64) ; R41.1 76.3,20.63 76.81,21.13 R43.2 76.94,21.99 77.15,22.19 77.6,22.19 77.81,21.99 77.81,18.47 77.52,18.19 74.42,18.19 74.4,18.21 74.38,18.21 73.97,18.62 73.08,18.62 72.29,17.83 72.29,16.43 71.84,15.99 70.38,15.99 70.37,15.98 69.53,15.98 65.8,12.26 64.07,12.26 62.8,10.99 62.8,9.34 62.69,9.24 v1(62.69,8.73) P3.32
I2C2_SDA: length 108.8
  TOP w0.133: S5.4 21.03,36.07 20.83,35.86 v1(20.83,35.43) 20.83,35 21.03,34.8 S5.5
  L3_SIG w0.102: v1(60.2,13.46) 60.2,13.9 55.55,18.54 50.1,18.54 49.47,19.18 44.83,19.18 42.9,21.11 42.9,25.81 33.53,35.18 21.08,35.18 v1(20.83,35.43)
  L8_SIG w0.14: v1(63.49,8.73) 63.46,8.73 62.42,7.68 61.53,7.68 61.48,7.73 61.48,7.73 59.69,9.52 59.69,12.95 v1(60.2,13.46)
  BOTTOM w0.133: R6.1 78.08,23.79 R45.2 78.08,22.27 78.24,22.11 78.24,18.37 77.68,17.81 74.25,17.81 73.88,18.18 73.17,18.18 72.67,17.67 72.67,16.28 72,15.61 71.88,15.61 71.87,15.6 69.69,15.6 65.96,11.88 64.29,11.88 63.32,10.91 63.32,10.07 63.33,10.05 63.33,9.4 63.49,9.24 v1(63.49,8.73) P3.34 ; U14.3 53.5,21.24 54.23,21.97 57.66,21.97 58.42,21.21 58.42,15.24 v1(60.2,13.46)
I2C_RPI_SCL: length 6.9
  BOTTOM w0.133: R98.1 53.37,28.92 53.37,28.3 54.1,27.56 54.1,26.29 54.73,25.66 R83.1 54.15,24.95 U14.7
I2C_RPI_SDA: length 5.3
  BOTTOM w0.133: R109.1 52.98,27.91 52.98,27.88 53.59,27.27 53.59,26.29 52.97,25.66 R81.1 53.5,25 U14.6
IOVDD: length 44.5
  TOP w0.133: U4.G1 75.9,20.14
  TOP w0.305: 75.9,20.14 75.9,19.76 v1(76.88,18.78) C33.1 ; v1(49.93,26.1) 50.5,26.67 P21.15
  TOP w0.381: U8.1 81.85,40.85 81.55,41.16 C63.2
  TOP w0.508: R80.1 v1(49.3,3.42) ; C63.2 v2(79.72,41.16) ; R68.2 v2(78.79,39.88) ; R67.2 v2(78.79,38.86) ; v1(64.13,31.12) R120.2 ; R87.1 R86.1 80.54,12.44 v1(81.51,13.41) ; R77.1 v1(31.37,4.16)
  L8_SIG w0.381: v1(79.47,20.46) 81.5,22.49 v1(81.5,24.2)
  BOTTOM w0.305: v2(48.41,25.86) 47.15,25.86 46.72,25.42 U5.8
  BOTTOM w0.381: U9.1 v2(68.78,31.28)
  BOTTOM w0.508: R43.1 76.94,18.84 v1(76.88,18.78) ; v2(44.85,26.37) 44.34,26.87 R61.2 R64.2 ; v1(66.21,31.2) 66.43,30.99 C70.2 67.76,30.99 68.06,31.28 v2(68.78,31.28) ; R47.2 v2(45.11,14.73) ; v1(46.25,14.22) R62.2 ; R45.1 79.75,23.8 79.76,23.79 80.43,23.79 80.84,24.2 v1(81.5,24.2) ; v1(50.55,19.3) 51.79,19.3 52.81,18.28 C88.2 54.22,18.28 54.8,18.86 U14.1 ; C52.1 v2(48.41,25.86) ; v2(46.83,30.04) 46.83,29.31 46.76,29.25 R55.2
LASERTEMP_I2C1_SCL: length 37.3
  TOP w0.133: P21.5 50.48,29.17 48.86,30.8 v1(48.86,31.18)
  BOTTOM w0.133: R94.1 76.47,31.75 76.29,31.93 U9.7 73.6,31.93 70.93,34.61 70.93,35.42 70.56,35.78 70.13,35.78 70.13,35.78 68.67,35.78 67.57,34.67 53.59,34.67 50.1,31.18 v1(48.86,31.18)
LASERTEMP_I2C1_SDA: length 42.1
  TOP w0.133: P21.7 50.84,28.67 50.78,28.73 50.42,28.73 50.36,28.79 50.32,28.79 47.81,31.31 v1(47.46,31.31)
  L3_SIG w0.102: v1(47.46,31.31) 53.78,37.63 69.24,37.63 v1(71.61,35.26)
  BOTTOM w0.133: R93.1 76.72,32.77 76.54,32.58 U9.6 73.61,32.58 73.41,32.79 73.41,34.84 72.99,35.26 v1(71.61,35.26)
LD1: length 17.5
  TOP w0.133: U4.A3 72.66,21.41 71.43,20.19 68.8,20.19 67.8,19.18 67.8,18.95 64.48,15.64 59.06,15.64 59.03,15.66 P21.60
LD2: length 17.6
  TOP w0.133: P21.52 63.82,17.67 66.52,20.37 66.52,20.98 67.2,21.66 70.37,21.66 71.45,22.74 71.94,22.74 72.26,22.41 U4.A5
LD3: length 17.5
  TOP w0.133: U4.A7 72.48,23.41 72.18,23.72 68.85,23.72 68.3,23.17 67.69,23.17 63.79,19.26 63.51,19.26 63.28,19.5 62.98,19.5 62.74,19.26 62.45,19.26 62.21,19.5 61.91,19.5 61.68,19.26 61.38,19.26 60.97,19.67 P21.44
LD4: length 17.6
  TOP w0.133: U4.A9 72.74,24.41 72.6,24.55 72.58,24.55 72.45,24.68 72,24.68 71.5,25.18 69.32,25.18 68.12,23.97 67.46,23.97 64.84,21.35 64.51,21.35 64.3,21.56 63.97,21.56 63.77,21.35 63.44,21.35 63.24,21.56 62.91,21.56 62.7,21.35 62.37,21.35 62.17,21.56 61.84,21.56 61.64,21.35 61.31,21.35 60.99,21.67 59.26,21.67 59.23,21.69 58.83,21.69 58.8,21.67 P21.36
LD5: length 51.4
  TOP w0.133: v1(72.14,30.61) 72.14,30.3 73.08,29.35 73.08,28.48 73.08,28.47 73.08,26.83
  TOP w0.14: U4.C11 73.08,26.23 73.08,26.65 73.08,26.83
  L8_SIG w0.102: v1(72.14,30.61) 72.86,29.88 73.42,29.88 75.31,27.99 75.31,22.55 78.82,19.03 78.82,17.37 80.21,15.98 83.92,15.98 85.23,14.67 85.23,12.94 85.65,12.52 87.51,12.52 89.33,14.33 92.3,14.33 94.29,16.32 96.82,16.32 99.99,13.16 100.91,13.16 v1(101.09,13.34)
  BOTTOM w0.133: v1(101.09,13.34) 101.27,13.16 R5.1
LD_EN1: length 4.4
  TOP w0.133: P21.1 51.18,30.18 50.67,30.68 50.67,32.14 LD_EN1.1
LD_EN2: length 5.6
  TOP w0.133: LD_EN2.1 50.04,31.63 50.04,30.47 50.84,29.67 P21.3
LED_BLUE: length 32.6
  TOP w0.133: R78.1 19.94,35.81 v1(20.83,36.7)
  L3_SIG w0.203: v1(45.55,39.37) 42.8,39.37 39.5,36.07 21.46,36.07 v1(20.83,36.7)
  BOTTOM w0.133: P4.8 v1(45.55,39.37)
LED_RED: length 36.2
  TOP w0.133: R79.1 v1(18.29,41.27)
  L3_SIG w0.203: v1(18.29,41.27) 21.72,41.27 26.42,36.58 38.99,36.58 42.55,40.13 46.85,40.13 v1(47.55,39.43)
  BOTTOM w0.133: P4.10 v1(47.55,39.43)
LS_I2C0_SCL: length 47.6
  TOP w0.133: 29.59,37.34 28.57,37.34 28.32,37.08 28.32,34.16 29.34,33.15 32.89,33.15 34.32,31.72 v1(44.85,31.72)
  L8_SIG w0.102: v1(45.69,23.52) 45.69,23.57 45.97,23.85 45.97,28.71 45.47,29.22 45.47,30.48 44.85,31.09 v1(44.85,31.72)
  BOTTOM w0.133: P4.15 53.55,36.54 50.16,33.15 46.28,33.15 v1(44.85,31.72) 44.85,31.22 45.47,30.61 45.47,29.56 R61.1 ; U5.6 45.42,23.79 v1(45.69,23.52)
LS_I2C0_SDA: length 45.5
  TOP w0.133: v1(46,31.12) 45.59,31.53 45.59,32.05 45.39,32.26 34.67,32.26 33.15,33.78 30.61,33.78 29.59,34.8
  L8_SIG w0.102: v1(46,31.12) 46,29.35 46.48,28.87 46.48,23.39 45.94,22.84 45.23,22.84 v1(44.55,23.52)
  BOTTOM w0.133: U5.5 44.77,23.74 v1(44.55,23.52) ; P4.17 55.55,36.5 54.48,35.43 53.47,35.43 50.55,32.51 47.38,32.51 v1(46,31.12) 46,28.95 R64.1
LS_I2C1_SCL: length 74.7
  TOP w0.133: R68.1 81.1,40.2 U8.2 84.66,40.2 85.09,39.78 85.09,37.49 83.74,36.14 78.02,36.14 77.39,36.78 68.53,36.78 67.56,35.81 67.56,34.01 67.87,33.7 v1(67.87,32.33) ; 29.59,38.61 29.97,38.61 31.98,36.6 52.43,36.6 53.61,35.42 v1(57.55,35.42)
  L3_SIG w0.102: v1(67.87,32.33) 67.36,32.85 60.8,32.85 58.23,35.42 v1(57.55,35.42)
  BOTTOM w0.133: U9.2 69.05,31.93 68.65,32.33 v1(67.87,32.33) ; P4.19 v1(57.55,35.42)
LS_I2C1_SDA: length 71.9
  TOP w0.133: v1(67.13,33.35) 67.13,36.01 68.33,37.21 77.52,37.21 78.15,36.58 83.63,36.58 84.71,37.65 84.71,39.17 84.32,39.55 U8.3 81.52,39.55 80.83,38.86 R67.1 ; v1(59.55,35.42) 59.55,35.42 58.93,34.8 53.21,34.8 51.94,36.07 29.59,36.07
  L3_SIG w0.102: v1(59.55,35.42) 61.62,33.35 v1(67.13,33.35)
  BOTTOM w0.133: P4.21 v1(59.55,35.42) ; U9.3 69.22,32.58 68.45,33.35 v1(67.13,33.35)
MIPI_CSI0_CLK_N: length 5.8
  BOTTOM w0.133: U11.16 51.33,10.63 51.33,9.96 51,9.63 50.72,9.63 50.72,9.63 50.06,9.63 49.93,9.5 49.93,9.31 50.06,9.18 50.9,9.18 51.26,8.82 51.26,8.73 51.26,8.49 51.31,8.45 51.31,7.38 P3.4
MIPI_CSI0_CLK_P: length 5.8
  BOTTOM w0.133: U11.17 50.99,10.64 50.99,10.1 50.86,9.97 49.92,9.97 49.59,9.64 49.59,9.17 49.92,8.84 50.77,8.84 50.93,8.68 50.93,8.46 50.88,8.41 50.88,7.38 P3.2
MIPI_CSI0_DATA0_N: length 5.6
  BOTTOM w0.133: P3.10 53.72,7.36 53.72,8.44 53.66,8.5 53.66,9.02 53.33,9.35 52.79,9.35 52.43,8.99 52.15,8.99 51.96,9.18 51.96,9.41 52.13,9.59 52.13,10.63 U11.14
MIPI_CSI0_DATA0_P: length 5.6
  BOTTOM w0.133: U11.15 51.79,10.63 51.79,9.72 51.62,9.55 51.62,9.04 52.01,8.66 52.57,8.66 52.93,9.02 53.19,9.02 53.32,8.88 53.32,8.5 53.26,8.44 53.26,7.37 P3.8
MIPI_CSI0_DATA1_N: length 5.7
  BOTTOM w0.133: P3.16 56.11,7.38 56.11,8.45 56.06,8.5 56.06,9.24 55.89,9.42 55.67,9.42 54.96,10.13 53.96,10.13 53.33,10.76 53.16,10.76 U11.12
MIPI_CSI0_DATA1_P: length 5.7
  BOTTOM w0.133: P3.14 55.68,7.38 55.68,8.45 55.72,8.5 55.72,8.89 54.82,9.8 53.82,9.8 53.19,10.43 52.72,10.43 52.56,10.58 U11.13
MIPI_CSI1_CLK_M: length 11.1
  L3_SIG w0.102: v3(73.99,12.19) 73.71,12.47 73.45,12.47 73.23,12.24 73.07,12.24 72.85,12.47 72.64,12.47 72.44,12.27 72.23,12.27 72.03,12.47 71.27,12.47 70.9,12.1 70.9,11.1 71.07,10.92 71.75,10.92 72.03,10.65 72.03,9.13 72.03,8.99 72.14,8.89 v3(72.39,8.89)
  BOTTOM w0.133: U7.16 72.97,12.43 73.75,12.43 v3(73.99,12.19) ; P3.56 72.29,8.05 72.11,8.23 72.11,8.61 v3(72.39,8.89)
MIPI_CSI1_CLK_P: length 11.1
  L3_SIG w0.102: v3(71.44,8.88) 71.7,8.88 71.8,8.99 71.8,9.13 71.8,10.55 71.66,10.69 70.97,10.69 70.66,11 70.66,12.19 71.17,12.7 73.73,12.7 v3(73.99,12.95)
  BOTTOM w0.133: v3(71.44,8.88) 71.7,8.62 71.7,8.28 71.49,8.07 P3.54 ; v3(73.99,12.95) 73.8,12.76 72.96,12.76 U7.17
MIPI_CSI1_DATA0_M: length 10.9
  BOTTOM w0.133: P3.44 67.49,8.26 67.26,8.5 67.26,8.73 67.39,8.86 67.56,8.86 67.69,9 67.69,9.26 67.55,9.41 67.39,9.41 67.28,9.51 67.28,9.77 66.88,10.17 66.88,11.04 67.47,11.62 72.45,11.62 72.49,11.59 U7.14
MIPI_CSI1_DATA0_P: length 11
  BOTTOM w0.133: U7.15 72.49,11.99 72.45,11.96 67.33,11.96 66.55,11.18 66.55,10.03 66.92,9.66 66.92,8.5 66.69,8.26 P3.42
MIPI_CSI1_DATA1_M: length 11
  BOTTOM w0.133: U7.12 73.05,10.61 73.05,10.21 72.71,9.88 72.1,9.88 71.77,10.21 71.77,10.48 71.64,10.62 71.3,10.62 71.17,10.48 71.17,10.21 70.84,9.88 70.32,9.88 69.96,10.24 69.96,10.43 69.83,10.57 68.84,10.57 68.68,10.4 68.68,10.01 68.86,9.83 69.3,9.83 69.62,9.51 69.64,9.51 69.7,9.45 70.03,9.45 70.16,9.32 70.16,8.92 70.03,8.8 69.84,8.8 69.7,8.66 69.7,7.38 P3.50
MIPI_CSI1_DATA1_P: length 11
  BOTTOM w0.133: P3.48 69.29,7.39 69.29,9.36 69.16,9.49 68.72,9.49 68.34,9.87 68.34,10.54 68.7,10.9 69.97,10.9 70.3,10.57 70.3,10.38 70.46,10.22 70.7,10.22 70.83,10.35 70.83,10.62 71.16,10.95 71.78,10.95 72.11,10.62 72.11,10.35 72.24,10.22 72.58,10.22 72.71,10.35 72.71,11.11 72.79,11.19 U7.13
PGOOD: length 6.4
  BOTTOM w0.133: U2.7 27.56,29.53 28.07,29.02 28.07,28.32 30.99,25.4 31.36,25.4 R16.2
PVOUT: length 17.1
  L8_SIG w0.508: v2(29.84,21.97) 29.84,23.75 28.32,25.27 28.32,29.34 29.13,30.15 29.13,30.23 29.84,30.94 v1(29.84,32.26)
  BOTTOM w0.133: R11.1 v2(29.84,21.97)
  BOTTOM w0.279: U2.3 28.88,31.53 C96.1 28.99,31.03 U2.4
PWM_SYNC: length 11.6
  TOP w0.133: v1(25.1,34.04) 22.05,30.99 18.54,30.99 17.27,29.72 R107.2
  BOTTOM w0.133: U2.25 v1(25.1,34.04)
REFB: length 6
  L2_GND w0.14: v5(73.9,24.41) v4(74.4,23.91)
  L3_SIG w0.203: v5(73.9,24.41) 73.9,24.52 v3(71.55,26.87)
  BOTTOM w0.133: v3(71.55,26.87) 71.88,26.87 C8.1
REFT: length 4
  L3_SIG w0.203: v5(74.4,23.41) 74.4,24.86 73.67,25.6 v3(73.67,26.44)
  BOTTOM w0.133: C2.1 v3(73.67,26.44)
RG: length 36.3
  L3_SIG w0.102: v5(76.4,23.91) 76.4,25.65 77.55,26.8 77.55,27.3 77.11,27.74 75.67,27.74 74.42,28.98 74.42,30.53 76.47,32.58 90.69,32.58 v1(92.82,30.45)
  BOTTOM w0.133: R69.1 94.6,26.06 95.64,27.1 95.64,28.63 93.82,30.45 v1(92.82,30.45)
RPI_CLKN: length 14.7
  TOP w0.133: P1.8 47.19,22.23 47.96,22.23 48.07,22.33 48.51,22.33 48.77,22.33 v1(48.99,22.12)
  BOTTOM w0.133: v1(48.99,22.12) 48.82,22.29 48.73,22.29 47.99,22.29 47.78,22.07 47.78,21.9 48.03,21.64 48.03,21.36 47.78,21.11 47.78,20.83 48.03,20.58 48.03,20.3 47.78,20.04 47.78,19.76 48.03,19.51 48.03,19.23 47.78,18.98 47.78,17.48 50.93,14.33 50.93,12.93 U11.2
RPI_CLKP: length 14.7
  TOP w0.133: P1.9 47.16,22.8 47.94,22.8 48.07,22.67 48.51,22.67 48.78,22.67 v1(48.97,22.87)
  BOTTOM w0.133: v1(48.97,22.87) 48.73,22.63 47.85,22.63 47.44,22.21 47.44,17.34 50.59,14.19 50.59,12.89 U11.1
RPI_DATA0N: length 14.8
  TOP w0.133: P1.2 47.85,16 48.19,16.33 48.37,16.33 48.66,16.04 48.66,14.22 49.02,13.86 49.73,13.86 50.1,14.22 50.1,16.5 49.83,16.77 49.83,17.06 v1(50.04,17.27)
  BOTTOM w0.133: U11.4 51.76,13.35 51.73,13.39 51.73,16.33 51.37,16.69 50,16.69 49.83,16.87 49.83,17.06 v1(50.04,17.27)
RPI_DATA0P: length 14.8
  TOP w0.133: P1.3 47.85,17 48.19,16.66 48.51,16.66 49,16.18 49,14.36 49.16,14.2 49.59,14.2 49.76,14.36 49.76,16.36 49.49,16.63 49.49,17.06 v1(49.28,17.27)
  BOTTOM w0.133: U11.3 51.36,13.35 51.39,13.39 51.39,16.2 51.23,16.36 50.95,16.36 50.81,16.22 50.81,16.08 50.68,15.95 50.41,15.95 50.28,16.08 50.28,16.22 50.15,16.36 49.86,16.36 49.49,16.73 49.49,17.06 v1(49.28,17.27)
RPI_DATA1N: length 14.7
  TOP w0.133: P1.5 47.85,19 48.19,19.33 48.37,19.33 48.48,19.22 48.48,18.9 48.83,18.56 49.54,18.56 49.87,18.89 49.87,20.1 v1(50.04,20.27)
  BOTTOM w0.133: U11.6 52.56,13.35 52.53,13.39 52.53,17.36 51.56,18.34 49.96,18.34 49.83,18.47 49.83,20.06 v1(50.04,20.27)
RPI_DATA1P: length 14.6
  TOP w0.133: v1(49.28,20.27) 49.53,20.02 49.53,19.02 49.4,18.9 48.96,18.9 48.82,19.04 48.82,19.36 48.51,19.66 48.19,19.66 47.85,20 P1.6
  BOTTOM w0.133: U11.5 52.16,13.35 52.19,13.39 52.19,17.22 51.42,18 49.82,18 49.49,18.33 49.49,18.87 49.33,19.02 49.21,19.02 49.07,19.16 49.07,19.42 49.21,19.56 49.36,19.56 49.49,19.69 49.49,20.06 v1(49.28,20.27)
RPI_SRS_CLKN: length 38
  L8_SIG w0.102: v3(74.93,15.34) 74.68,15.34 74.58,15.44 74.58,15.69 72.92,17.34 71.11,17.34 70.29,18.16 53.05,18.16 51.2,16.31 51.06,16.31 50.74,16.62 50.4,16.62 50.12,16.34 50.12,16 50.41,15.72 50.41,15.51 50.26,15.37 50.12,15.37 49.9,15.59 49.56,15.59 49.28,15.31 49.28,14.97 49.5,14.75 49.5,14.61 49.35,14.46 49.21,14.46 48.99,14.68 48.65,14.68 48.37,14.4 48.37,14.06 48.59,13.84 48.59,13.7 48.34,13.45 48.19,13.45 v1(47.93,13.71)
  BOTTOM w0.133: v3(74.93,15.34) 74.62,15.04 74.62,14.24 74.65,14.21 U7.23 ; v1(47.93,13.71) 48.14,13.5 48.73,13.5 49.19,13.04 49.19,12.49 49.32,12.35 49.51,12.35 49.54,12.39 U11.23
RPI_SRS_CLKP: length 38
  L8_SIG w0.102: v3(73.99,15.34) 74.24,15.34 74.34,15.44 ; 74.34,15.44 74.34,15.44 74.34,15.44 ; 74.34,15.44 74.34,15.59 72.82,17.11 71.02,17.11 70.2,17.93 53.15,17.93 53.02,17.79 53.02,17.56 52.85,17.39 52.61,17.39 52.44,17.22 52.44,16.98 52.27,16.81 52.04,16.81 51.87,16.64 51.87,16.41 51.7,16.24 51.46,16.24 51.3,16.07 50.96,16.07 50.65,16.39 50.5,16.39 50.36,16.24 50.36,16.1 50.64,15.82 50.64,15.42 50.36,15.13 50.02,15.13 49.8,15.35 49.66,15.35 49.51,15.21 49.51,15.06 49.73,14.85 49.73,14.51 49.45,14.23 49.11,14.23 48.89,14.44 48.75,14.44 48.61,14.3 48.61,14.16 48.82,13.94 48.82,13.6 48.43,13.21 48.19,13.21 v1(47.93,12.95)
  BOTTOM w0.133: v1(47.93,12.95) 48.14,13.16 48.59,13.16 48.85,12.9 48.85,12.35 49.18,12.02 49.51,12.02 49.54,11.99 U11.22 ; U7.22 74.25,14.21 74.29,14.24 74.29,15.05 v3(73.99,15.34)
RPI_SRS_DATA0N: length 38.2
  L8_SIG w0.102: v1(46.23,9.17) 46.49,9.43 46.49,9.99 52.66,16.17 72.22,16.17 72.94,15.45 73.08,15.45 73.24,15.6 v3(73.25,15.6)
  BOTTOM w0.133: v3(73.25,15.6) 73.24,15.22 73.37,15.08 73.82,14.63 73.82,14.24 73.86,14.21 U7.21 ; v1(46.23,9.17) 46.44,9.38 46.44,10.69 47.3,11.55 49.51,11.55 49.54,11.59 U11.21
RPI_SRS_DATA0P: length 38.2
  L8_SIG w0.102: v1(46.99,9.17) 46.73,9.43 46.73,9.9 46.81,9.98 46.95,9.98 47.06,9.87 47.21,9.87 47.35,10.01 47.35,10.16 47.24,10.27 47.24,10.41 47.38,10.55 47.53,10.55 47.64,10.44 47.78,10.44 47.92,10.59 47.92,10.73 47.81,10.84 47.81,10.98 47.96,11.13 48.1,11.13 48.21,11.02 48.36,11.02 48.5,11.16 48.5,11.31 48.39,11.42 48.39,11.56 52.76,15.93 72.12,15.93 72.77,15.28 72.77,15.14 v3(72.62,14.99)
  BOTTOM w0.133: U7.20 73.46,14.21 73.49,14.24 73.49,14.49 73.13,14.85 73,14.98 v3(72.62,14.99) ; U11.20 49.54,11.19 49.51,11.22 47.44,11.22 46.78,10.55 46.78,9.38 v1(46.99,9.17)
RPI_SRS_DATA1N: length 38.1
  L8_SIG w0.102: v3(71.3,13.8) 71.51,14.01 71.51,14.16 70.91,14.75 53.06,14.75 52.92,14.62 52.92,14.47 52.98,14.41 52.98,14.27 52.84,14.13 52.69,14.13 52.63,14.18 52.49,14.18 52.32,14.02 52.32,13.87 52.87,13.33 52.87,12.99 52.59,12.71 52.25,12.71 51.7,13.25 51.56,13.25 51.41,13.11 51.41,12.96 51.9,12.48 51.9,12.14 51.61,11.86 51.28,11.86 50.79,12.34 50.65,12.34 50.51,12.2 50.51,12.06 50.99,11.57 50.99,11.24 50.71,10.95 50.37,10.95 49.89,11.44 49.74,11.44 49.6,11.29 49.6,11.15 50.08,10.67 50.08,10.33 49.8,10.05 49.46,10.05 48.98,10.53 48.83,10.53 48.58,10.27 48.58,9.91 v1(48.84,9.65)
  BOTTOM w0.133: U7.18 72.89,13.23 72.36,13.23 71.79,13.8 v3(71.3,13.8) ; v1(48.84,9.65) 48.63,9.86 48.63,10.32 48.77,10.45 50.45,10.45 50.56,10.56 U11.18
RPI_SRS_DATA1P: length 38.1
  L8_SIG w0.102: v1(48.08,9.65) 48.34,9.91 48.34,10.37 48.74,10.76 49.07,10.76 49.56,10.28 49.7,10.28 49.84,10.43 49.84,10.57 49.36,11.05 49.36,11.39 49.64,11.67 49.98,11.67 50.46,11.19 50.61,11.19 50.75,11.33 50.75,11.48 50.27,11.96 50.27,12.3 50.55,12.58 50.89,12.58 51.37,12.1 51.52,12.1 51.66,12.24 51.66,12.39 51.18,12.87 51.18,13.21 51.46,13.49 51.8,13.49 52.34,12.94 52.49,12.94 52.63,13.09 52.63,13.23 52.09,13.78 52.09,14.11 52.96,14.99 71.01,14.99 71.67,14.32 71.82,14.32 v3(72.03,14.53)
  BOTTOM w0.133: v3(72.03,14.53) 72.03,14.04 72.5,13.57 72.92,13.57 73.05,13.7 U7.19 ; v1(48.08,9.65) 48.3,9.86 48.3,10.45 48.63,10.79 U11.19
RSTB_SYNC: length 37
  TOP w0.133: C24.1 60.89,23.16 60.66,23.39 v1(60.66,24.1)
  L3_SIG w0.102: v5(75.9,21.91) 75.59,21.6 74.81,21.6 72.39,19.18 72.39,17.93 71.98,17.52 70.35,17.52 69.5,17.52 v1(68.28,18.73)
  L8_SIG w0.203: v1(61.55,35.42) 61.55,32.7 61.09,32.23 61.09,25.41 60.66,24.99 v1(60.66,24.1) 60.66,24.08 61.12,23.62 65.3,23.62 67.72,21.2 67.72,19.29 v1(68.28,18.73)
  BOTTOM w0.133: P4.23 v1(61.55,35.42)
RUN: length 5.9
  BOTTOM w0.133: U2.15 23.19,29.03 22.86,28.7 22.86,27.69 22.1,26.92 20.96,26.92 R116.1
SEL: length 121.3
  TOP w0.133: v1(56.64,10.41) 57.48,9.58 64.72,9.58 65.38,10.24 72.69,10.24 72.92,10.01 72.92,9.31 v1(72.95,9.29) ; v1(5.88,38.52) S1.2
  L3_SIG w0.305: v1(72.95,9.29) 72.95,9.25 73.03,9.17 73.03,8.12 72.38,7.47 65.43,7.47 64.8,8.1 64.8,8.97 62.94,10.84 60.6,10.84 60.17,10.41 57.73,10.41 57.07,11.07 56.39,11.07 55.8,10.49 54.91,10.49 54.55,10.86 25.23,10.86 21.89,7.52 18.55,7.52 14.34,11.72 14.34,22.99 12.91,24.42 11.39,24.42 8.72,27.09 8.72,35.68 v1(5.88,38.52)
  BOTTOM w0.133: v1(56.64,10.41) 56.41,10.64 54.08,10.64 53.53,11.19 U11.11 ; v1(72.95,9.29) 72.95,9.6 73.46,10.11 U7.11
SPI1_CLK: length 43.2
  TOP w0.133: v1(65.74,9.68) 64.97,8.92 64.97,5.74 61.59,2.36 R113.1
  L8_SIG w0.102: v1(60.7,11.78) 63.04,11.78 65.15,9.68 v1(65.74,9.68)
  BOTTOM w0.133: v1(60.7,11.78) 63.09,14.17 63.09,14.77 63.09,14.77 64.15,15.83 65.7,15.83 67.65,17.78 68.31,17.78 68.67,18.14 69.38,18.14 69.68,18.45 69.68,19.27 70.35,19.93 70.35,20.97 71.01,21.63 72.51,21.63 73.51,20.63 R28.1
SPI1_CS_N: length 21.7
  TOP w0.133: R89.2 67.66,10.74 65.15,10.74 64.59,10.19 v1(61.95,10.19)
  L3_SIG w0.102: v1(53.09,4.27) 53.09,5.31 55.21,7.43 59.19,7.43 v1(61.95,10.19)
  BOTTOM w0.133: v1(53.09,4.27) P3.7
SPI1_MISO: length 59.1
  L3_SIG w0.102: v1(50.69,4.24) 51.33,3.61 55.99,3.61 58.28,5.9 73.65,5.9 75.35,7.59 78.28,7.59 83.22,12.53 83.22,18.14 83.39,18.31 83.63,18.31 v1(83.88,18.05)
  BOTTOM w0.133: v1(50.69,4.24) P3.1 ; R88.2 77.78,26.25 78.14,25.89 81.89,25.89 85.09,22.68 85.09,18.9 84.6,18.41 84.24,18.41 v1(83.88,18.05)
SPI1_MOSI: length 53.5
  L3_SIG w0.102: v1(54.69,4.27) 56.79,6.37 73.46,6.37 75.29,8.2 78.23,8.2 82.75,12.73 82.75,18.33 83.2,18.78 83.47,18.78 v1(83.85,19.16)
  BOTTOM w0.133: v1(83.85,19.16) 83.86,19.16 84.15,18.87 84.52,18.87 84.71,19.06 84.71,22.53 81.82,25.42 78.09,25.42 77.74,25.06 R3.1 ; v1(54.69,4.27) P3.11
SUB: length 23.6
  TOP w0.133: U1.16 95.16,18.74 v1(94.83,18.41) 94.51,18.74 U1.15
  L3_SIG w0.102: v1(104.87,28.14) 95.14,18.41 v1(94.83,18.41)
  BOTTOM w0.133: D5.C 106.4,29.39 106.01,29 R29.1 105.73,29 v1(104.87,28.14) ; C59.2 R42.1 95.5,19.43 D4.C 94.53,18.72 v1(94.83,18.41)
SUBOUT: length 13.5
  TOP w0.133: U1.18 96.46,18.75 96.79,18.41 97.77,18.41 97.82,18.47 99.95,18.47 103.35,21.87 v1(103.4,21.87)
  BOTTOM w0.133: R7.1 v1(103.4,21.87)
SW1: length 4.7
  L8_SIG w0.508: v1(22.48,30.53) v1(22.48,33.28)
  BOTTOM w0.133: v1(22.48,30.53) 22.48,30.53 U2.18 ; U2.21 22.91,32.03 22.67,32.27 22.67,32.32
SW2: length 4.7
  L8_SIG w0.508: v1(28.32,30.49) 28.29,30.52 v1(28.29,33.24)
  BOTTOM w0.133: 28.04,32.17 27.91,32.03 U2.2 ; U2.5 28.27,30.53 v1(28.32,30.49)
TAL1: length 19.8
  TOP w0.133: v1(59.99,16.66) P21.56
  L3_SIG w0.102: v1(67.13,19.79) 67.13,19.92 68.14,20.93 68.66,20.93 69.11,20.48 70.29,20.48 71.01,21.2 73.19,21.2 v5(73.9,21.91)
  BOTTOM w0.133: v1(67.13,19.79) 67.13,18.36 66.23,17.46 63.54,17.46 62.31,16.23 61.24,16.23 60.81,16.66 v1(59.99,16.66)
TAL2: length 19.8
  TOP w0.133: v1(59.95,18.66) 59.94,18.67 P21.48
  L3_SIG w0.102: v5(73.4,21.91) 73.08,21.59 68.02,21.59 v1(67.14,20.71)
  BOTTOM w0.133: v1(59.95,18.66) 60.02,18.59 60.02,18.39 60.15,18.26 61.82,18.26 62.04,18.48 62.04,19.1 62.25,19.3 62.65,19.3 62.86,19.1 62.86,18.66 63.06,18.46 63.31,18.46 63.51,18.66 63.51,19.1 63.71,19.3 64.12,19.3 64.32,19.1 64.32,18.66 64.53,18.46 64.88,18.46 v1(67.14,20.71)
TAL3: length 19.8
  TOP w0.133: v1(60,20.72) 59.95,20.67 P21.40
  L3_SIG w0.102: v1(69.68,24.63) 70.6,24.63 71.32,23.91 v5(73.4,23.91)
  BOTTOM w0.133: v1(60,20.72) 60,21.5 60.14,21.64 60.35,21.64 60.55,21.44 60.55,21.09 60.76,20.89 61.14,20.89 61.34,21.09 61.34,21.41 61.57,21.64 62.56,21.64 62.76,21.44 62.76,21.17 62.99,20.94 63.37,20.94 63.58,21.15 63.58,21.44 63.78,21.64 65.94,21.64 67.92,23.62 68.67,23.62 v1(69.68,24.63)
TAL4: length 19.8
  TOP w0.133: P21.32 59.63,22.67 v1(59.69,22.73)
  L3_SIG w0.102: v5(73.9,23.91) 72.61,25.2 69.29,25.2 68.68,24.58 67.9,24.58 67.88,24.57 v1(67.75,24.57)
  BOTTOM w0.133: v1(67.75,24.57) 66.22,23.04 63.99,23.04 63.79,23.24 63.79,23.62 63.58,23.83 63.18,23.83 62.97,23.62 62.97,23.24 62.77,23.04 62.37,23.04 62.16,23.24 62.16,23.62 61.96,23.83 61.55,23.83 61.35,23.62 61.35,23.24 61.15,23.04 59.99,23.04 v1(59.69,22.73)
TAL5: length 52.3
  L3_SIG w0.102: v1(68.07,25.68) 69.01,26.62 70.36,26.62 71.21,27.47 72.1,27.47 72.61,26.95 73.94,26.95 74.27,26.62 74.27,25.6 74.9,24.97 v5(74.9,23.91)
  L8_SIG w0.102: v1(68.07,25.68) 68.07,25.1 69.93,23.24 73.95,23.24 78.26,18.93 78.26,17.14 79.96,15.44 83.77,15.44 84.76,14.46 84.76,12.74 85.49,12.01 87.72,12.01 89.54,13.83 92.51,13.83 94.44,15.76 96.37,15.76 v1(96.89,15.24)
  BOTTOM w0.133: v1(96.89,15.24) 95.89,16.24 R40.1 95.89,18.03 R42.2
TAVDD: length 21.1
  TOP w0.508: v1(69.14,14.16) C7.1 R65.1
  L3_SIG w0.102: v1(69.14,14.16) 66.17,17.14 66.17,22.69 66.56,23.09 70.17,23.09 70.59,22.68 73.46,22.68 73.69,22.45 74.44,22.45 v5(74.9,22.91)
TEMP_CT_AFE: length 58.4
  TOP w0.133: R87.2 U13.6 85.73,10.54 86.61,11.43 86.61,13.57 v1(87.5,14.45)
  L8_SIG w0.102: v1(61.55,39.89) 64.72,43.05 73.76,43.05 86.72,30.09 86.72,20.27 87.5,19.49 v1(87.5,14.45)
  BOTTOM w0.133: P4.24 v1(61.55,39.89)
TEMP_CT_LASER: length 26
  TOP w0.133: P21.11 50.84,27.67 50.81,27.65 49.72,27.65 49.06,28.31 v1(49.06,29.31)
  L3_SIG w0.102: v1(63.55,35.42) 63.01,35.42 61.59,36.83 54.1,36.83 50.67,33.4 50.67,30.93 v1(49.06,29.31)
  BOTTOM w0.133: P4.25 v1(63.55,35.42)
TEMP_INT_AFE: length 53.7
  TOP w0.133: v1(86.43,14.28) 85.98,13.83 85.98,12.19 85.6,11.81 U13.5 R86.2
  L8_SIG w0.102: v1(86.43,14.28) 86.43,18.6 85.47,19.56 85.47,24.82 85.85,25.2 85.85,30.29 73.64,42.51 66.18,42.51 v1(63.55,39.89)
  BOTTOM w0.133: P4.26 v1(63.55,39.89)
TEMP_INT_LASER: length 27.4
  TOP w0.133: P21.13 50.7,27.17 50.64,27.11 v1(50.13,27.11)
  L3_SIG w0.102: v1(65.55,35.42) 64.92,34.78 63.01,34.78 61.47,36.32 54.36,36.32 51.31,33.27 51.31,27.94 50.47,27.11 v1(50.13,27.11)
  BOTTOM w0.133: P4.27 v1(65.55,35.42)
